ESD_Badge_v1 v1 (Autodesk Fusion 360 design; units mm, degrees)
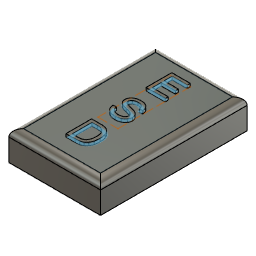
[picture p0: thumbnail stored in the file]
box_primitive "BoxPrimitive4" DistanceX 40 DistanceY 25 DistanceZ 8 OffsetDistanceX 0 OffsetDistanceY 0
fillet "Fillet2" radius 2
sketch "Sketch8" plane through (0, 0, 0) normal (0, -1, 0) x axis (1, 0, 0)
  line L1 (-12.493, 20.1588) -> (12.507, 20.1588)
  line L2 (-12.493, -19.8412) -> (-12.493, 20.1588)
  line L3 (12.507, -19.8412) -> (-12.493, -19.8412)
  line L4 (12.507, 20.1588) -> (12.507, -19.8412)
  line L5 (10.4937, 13.2062) -> (-10.5063, 13.2062)
  line L6 (10.4937, -11.7938) -> (10.4937, 13.2062)
  line L7 (-10.5063, -11.7938) -> (10.4937, -11.7938)
  line L8 (-10.5063, 13.2062) -> (-10.5063, -11.7938)
  point P6 (-10.5063, 13.2062)
  point P7 (10.4937, 13.2062)
  point P9 (-10.5063, -11.7938)
  horizontal L5
  vertical L6
  horizontal L7
  vertical L8
  dimension "d30" distance P6 P7 = 21
  dimension "d31" distance P6 P9 = 25
extrude "Extrude1" cut sketch "Sketch8" profile of L5 L6 L7 L8 against normal blind 5
hole "Hole1" HoleDepth 4 HoleDiameter 2.271 TipAngle 180
hole "Hole2" HoleDepth 4 HoleDiameter 2.271 TipAngle 180
sketch "Sketch9" plane through (0, 8, 0) normal (0, 1, 0) x axis (-1, 0, 0)
  dimension "d40" = 7
extrude "Extrude3" add sketch "Sketch9" along normal blind 0.6
extrude "Extrude2" add sketch "Sketch9" along normal blind 0.8
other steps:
thread "Thread1"
thread "Thread2"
